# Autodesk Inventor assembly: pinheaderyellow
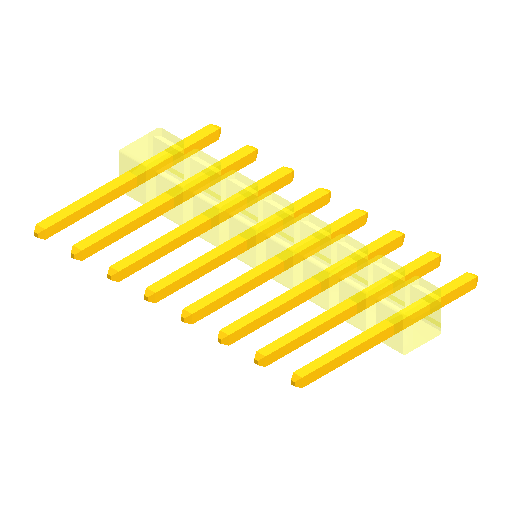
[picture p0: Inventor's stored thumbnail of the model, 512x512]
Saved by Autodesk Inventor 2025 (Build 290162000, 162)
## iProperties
Created: 2025-05
Part Number: pinheaderyellow
Document SubType Name: Assembly
Designer: R5800u
Author: R5800u
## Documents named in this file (3)
- C:\Users\R5800u\Desktop\drone\c3\ESP32-C3 Super Mini breakout expansion board module -Assembly\pinheaderyellow.iam
- C:\Users\R5800u\Desktop\drone\c3\ESP32-C3 Super Mini breakout expansion board module -Assembly\COMPOUND.iam
- C:\Users\R5800u\Desktop\drone\c3\ESP32-C3 Super Mini breakout expansion board module -Assembly\COMPOUND_1.iam
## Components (2 placed, 2 different names)
1. 10 [sub-assembly]
2. 19 [sub-assembly]
